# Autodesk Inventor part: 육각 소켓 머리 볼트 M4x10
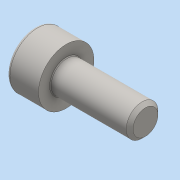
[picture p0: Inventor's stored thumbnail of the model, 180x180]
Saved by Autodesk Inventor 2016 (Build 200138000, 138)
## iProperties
Created: 2024-08
Part Number: 육각 소켓 머리 볼트 M4x10
Material: 일반
Description: 6각머리 태핑 나사
Document SubType Name: Modeling
Designer: pc-7
Density: 1 g/cm^3
Appearance: 기본값
Author: jhkim
Sending System: Autodesk Inventor 2025
Preprocessor: ST-DEVELOPER v20
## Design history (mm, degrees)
node "육각 소켓 머리 볼트 M4x101"
node "솔리드1"
body "Solid1"
